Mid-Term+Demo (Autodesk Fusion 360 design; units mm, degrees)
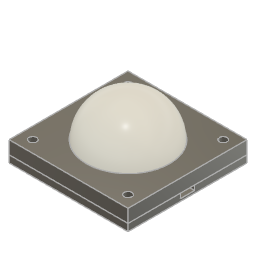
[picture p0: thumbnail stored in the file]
sketch "Sketch1" plane through (0, 0, 0) normal (0, 1, 0) x axis (1, 0, 0)
  line L1 (0, 45) -> (0, 0)
  line L2 (0, -35) -> (0, 0)
  circle C1 centre (0, 0) radius 15
  circle C2 centre (0, 0) radius 17.5
  circle C3 centre (0, 0) radius 22.5
  point P1 (0, 0)
  point P2 (0, 0)
  point P4 (0, 0)
  point P6 (0, 0)
  coincident P1 P2
  concentric C1 C2
  coincident P1 P4
  vertical L1
  coincident P2 P6
  parallel L1 L2
  concentric C2 C3
  dimension "d1" diameter C1 = 30
  dimension "d2" diameter C2 = 35
  dimension "d4" diameter C3 = 45
revolve "Revolve1" sketch "Sketch1" AlongAngle 180 bodies "Membrane"
extrude "Extrude1" add blind -5
move "Move1"
sketch "Sketch2" plane through (0, 0, 0) normal (0, 1, 0) x axis (1, 0, 0)
  line L1 (25, 25) -> (-25, 25)
  line L2 (25, -25) -> (25, 25)
  line L3 (-25, -25) -> (25, -25)
  line L4 (-25, 25) -> (-25, -25)
  circle C1 centre (0, 0) radius 22.5
  point P1 (0, 0)
  point P2 (0, 0)
  coincident P1 P2
  horizontal L1
  vertical L2
  horizontal L3
  vertical L4
  dimension "d7" diameter C1 = 45
extrude "Extrude2" new body sketch "Sketch2" along normal blind 3.5 bodies "Cap"
sketch "Sketch3" plane through (0, 3.5, 0) normal (0, 1, 0) x axis (-1, 0, 0)
  line L1 (-25, 25) -> (25, 25)
  line L2 (-25, -25) -> (-25, 25)
  line L3 (25, -25) -> (-25, -25)
  line L4 (25, 25) -> (25, -25)
  circle C1 centre (0, 0) radius 22.5
  circle C2 centre (0, 0) radius 17.5
  concentric C1 C2
  dimension "d10" diameter C2 = 35
extrude "Extrude3" add sketch "Sketch3" along normal blind 2
extrude "Extrude4" new body sketch "Sketch2" against normal blind 8 bodies "Base"
sketch "Sketch4" plane through (0, 0, 0) normal (0, 1, 0) x axis (-1, 0, 0)
  line L1 (-25, 25) -> (25, 25)
  line L2 (-25, -25) -> (-25, 25)
  line L3 (25, -25) -> (-25, -25)
  line L4 (25, 25) -> (25, -25)
  line L5 (-6, -0.9751) -> (-25, -0.9751)
  line L6 (0, 1.0068) -> (0, -0.9751)
  line L7 (-25, 1.0068) -> (-6, 1.0068)
  line L8 (0, 8) -> (0, 0)
  line L9 (5.4, 8) -> (-6, 8)
  line L10 (5.4, -8) -> (5.4, 8)
  line L11 (-6, -8) -> (5.4, -8)
  line L12 (-6, -0.9751) -> (-6, -8)
  line L13 (-6, 8) -> (-6, 1.0068)
  circle C1 centre (0, 0) radius 17.5
  circle C2 centre (0, 0) radius 20
  point P6 (-25, -0.9751)
  point P9 (-25, 1.0068)
  point P1 (0, 0)
  point P10 (0, 0)
  point P16 (-6, 1.0068)
  point P18 (0, 0)
  point P19 (0, 0)
  point P11 (0, 8)
  point P12 (-6, 8)
  point P13 (5.4, 8)
  coincident L2 P6
  perpendicular L2 L5
  perpendicular L5 L6
  coincident L2 P9
  perpendicular L2 L7
  coincident P1 P10
  parallel L6 L8
  horizontal L9
  vertical L10
  horizontal L11
  vertical L12
  coincident P16 L12
  collinear L12 L13
  coincident P1 P18
  coincident P10 P19
  dimension "d17" distance P10 P11 = 8
  dimension "d18" distance P12 P13 = 11.4
  dimension "d19" distance L2 L13 = 19
  dimension "d20" diameter C1 = 35
  dimension "d23" diameter C2 = 40
extrude "Extrude6" cut sketch "Sketch4" profile of L2 L5 L7 L9 L10 L11 L13 C1 C2 against normal blind 1
sketch "Sketch5" plane through (0, 5.5, 0) normal (0, 1, 0) x axis (-1, 0, 0)
  line L1 (25, 25) -> (25, -25)
  line L2 (-25, 25) -> (25, 25)
  line L3 (-25, -25) -> (-25, 25)
  line L4 (25, -25) -> (-25, -25)
  line L5 (-25, 25) -> (25, -25)
  line L6 (25, 25) -> (-25, -25)
  line L7 (-20, -20) -> (20, -20)
  line L8 (-20, 20) -> (-20, -20)
  line L9 (20, 20) -> (-20, 20)
  line L10 (20, -20) -> (20, 20)
  circle C1 centre (0, 0) radius 17.5
  point P3 (25, -25)
  point P7 (25, -25)
  point P5 (-25, 25)
  point P8 (-25, 25)
  point P6 (-25, -25)
  point P9 (-25, -25)
  point P4 (25, 25)
  point P10 (25, 25)
  point P13 (-20, 20)
  point P11 (20, -20)
  coincident P3 P7
  coincident P5 P8
  coincident P6 P9
  coincident P4 P10
  horizontal L7
  vertical L8
  horizontal L9
  vertical L10
  coincident L5 P13
  coincident L5 P11
sketch "Sketch6" plane through (0, -8, 0) normal (0, -1, 0) x axis (1, 0, 0)
  line L1 (-25, 25) -> (25, 25)
  line L2 (-25, -25) -> (-25, 25)
  line L3 (25, -25) -> (-25, -25)
  line L4 (25, 25) -> (25, -25)
  line L5 (-18.35, 22.6847) -> (-16.8, 20)
  line L6 (-21.45, 22.6847) -> (-18.35, 22.6847)
  line L7 (-23, 20) -> (-21.45, 22.6847)
  line L8 (-21.45, 17.3153) -> (-23, 20)
  line L9 (-18.35, 17.3153) -> (-21.45, 17.3153)
  line L10 (-16.8, 20) -> (-18.35, 17.3153)
  line L11 (21.65, 22.6847) -> (23.2, 20)
  line L12 (18.55, 22.6847) -> (21.65, 22.6847)
  line L13 (17, 20) -> (18.55, 22.6847)
  line L14 (18.55, 17.3153) -> (17, 20)
  line L15 (21.65, 17.3153) -> (18.55, 17.3153)
  line L16 (23.2, 20) -> (21.65, 17.3153)
  line L17 (-22.6847, -18.45) -> (-20, -16.9)
  line L18 (-22.6847, -21.55) -> (-22.6847, -18.45)
  line L19 (-20, -23.1) -> (-22.6847, -21.55)
  line L20 (-17.3153, -21.55) -> (-20, -23.1)
  line L21 (-17.3153, -18.45) -> (-17.3153, -21.55)
  line L22 (-20, -16.9) -> (-17.3153, -18.45)
  line L23 (17.3153, -18.45) -> (20, -16.9)
  line L24 (17.3153, -21.55) -> (17.3153, -18.45)
  line L25 (20, -23.1) -> (17.3153, -21.55)
  line L26 (22.6847, -21.55) -> (20, -23.1)
  line L27 (22.6847, -18.45) -> (22.6847, -21.55)
  line L28 (20, -16.9) -> (22.6847, -18.45)
  point P6 (-16.8, 20)
  point P12 (-19.9, 20)
  point P13 (23.2, 20)
  point P19 (20.1, 20)
  point P20 (-20, -16.9)
  point P26 (-20, -20)
  point P27 (20, -16.9)
  point P33 (20, -20)
  dimension "d24" distance P6 P12 = 3.1
  dimension "d25" distance P13 P19 = 3.1
  dimension "d26" distance P20 P26 = 3.1
  dimension "d27" distance P27 P33 = 3.1
extrude "Extrude7" cut sketch "Sketch6" profile of L5 L6 L7 L8 L9 L10 L11 L12 L13 L14 L15 L16 L17 L18 L19 L20 L21 L22 L23 L24 L25 L26 L27 L28 against normal blind 2.8
hole "Hole1" HoleDepth 12 HoleDiameter 3.2 TipAngle 180
extrude "Extrude8" cut sketch "Sketch4" profile of L5 L7 C1 C2 against normal blind 0.5
sketch "Sketch7" plane through (0, 0, 0) normal (0, 1, 0) x axis (1, 0, 0)
  line L1 (25, 25) -> (-25, 25)
  line L2 (25, -25) -> (25, 25)
  line L3 (-25, -25) -> (25, -25)
  line L4 (-25, 25) -> (-25, -25)
  horizontal L1
  vertical L2
  horizontal L3
  vertical L4
combine "Combine1"
sketch "Sketch8" plane through (0, 0, 0) normal (0, -1, 0) x axis (1, 0, 0)
  line L1 (25, 25) -> (-25, 25)
  line L2 (25, -25) -> (25, 25)
  line L3 (-25, -25) -> (25, -25)
  line L4 (-25, 25) -> (-25, -25)
  circle C1 centre (0, 0) radius 15
  circle C2 centre (0, 0) radius 22.5
  circle C3 centre (-0.0783, 18.7498) radius 3.75
  circle C4 centre (-0.0153, -20.25) radius 2.25
  point P1 (0, 0)
  point P7 (0, 0)
  horizontal L1
  vertical L2
  horizontal L3
  vertical L4
  coincident P1 P7
  tangent C1 C3
  dimension "d39" diameter C2 = 45
extrude "Extrude1" add sketch "Sketch8" profile of C1 L1 L2 L3 L4 along normal blind 5
extrude "Extrude2" cut sketch "Sketch8" profile of C2 C3 C4 along normal blind 10
sketch "Sketch9" plane through (0, -5, 0) normal (0, -1, 0) x axis (1, 0, 0)
  line L1 (25, -25) -> (-25, -25)
  line L2 (25, 25) -> (25, -25)
  line L3 (-25, 25) -> (25, 25)
  line L4 (-25, -25) -> (-25, 25)
  line L5 (25, -25) -> (-25, 25)
  line L6 (-25, -25) -> (25, 25)
  line L7 (21, 21) -> (-21, 21)
  line L8 (21, -21) -> (21, 21)
  line L9 (-21, -21) -> (21, -21)
  line L10 (-21, 21) -> (-21, -21)
  circle C1 centre (-0.0783, 18.7498) radius 3.75
  arc A1 centre (0, 0) radius 22.5 clockwise from (-0.0034, -22.5) to (-0.0307, -22.5)
  arc A2 centre (-0.0153, -20.25) radius 2.25 clockwise from (-0.0307, -22.5) to (-0.0034, -22.5)
  circle C2 centre (0, 0) radius 22.5
  point P1 (0, 0)
  point P11 (0, 0)
  point P10 (-25, 25)
  point P12 (-25, 25)
  point P8 (25, -25)
  point P13 (25, -25)
  point P9 (25, 25)
  point P14 (25, 25)
  point P7 (-25, -25)
  point P15 (-25, -25)
  point P18 (21, -21)
  point P16 (-21, 21)
  coincident P1 P11
  tangent C1 C2
  coincident P10 P12
  coincident P8 P13
  coincident P9 P14
  coincident P7 P15
  horizontal L7
  vertical L8
  horizontal L9
  vertical L10
  coincident L5 P18
  coincident L5 P16
hole "Hole1" HoleDepth 31 HoleDiameter 3.2 TipAngle 180
sketch "Sketch10" plane through (0, 25, 0) normal (0, 1, 0) x axis (-1, 0, 0)
  line L1 (-25, 25) -> (25, 25)
  line L2 (-25, -25) -> (-25, 25)
  line L3 (25, -25) -> (-25, -25)
  line L4 (25, 25) -> (25, -25)
  line L5 (23.6847, -22.55) -> (21, -24.1)
  line L6 (23.6847, -19.45) -> (23.6847, -22.55)
  line L7 (21, -17.9) -> (23.6847, -19.45)
  line L8 (18.3153, -19.45) -> (21, -17.9)
  line L9 (18.3153, -22.55) -> (18.3153, -19.45)
  line L10 (21, -24.1) -> (18.3153, -22.55)
  line L11 (-18.3153, -22.55) -> (-21, -24.1)
  line L12 (-18.3153, -19.45) -> (-18.3153, -22.55)
  line L13 (-21, -17.9) -> (-18.3153, -19.45)
  line L14 (-23.6847, -19.45) -> (-21, -17.9)
  line L15 (-23.6847, -22.55) -> (-23.6847, -19.45)
  line L16 (-21, -24.1) -> (-23.6847, -22.55)
  line L17 (-18.3153, 19.45) -> (-21, 17.9)
  line L18 (-18.3153, 22.55) -> (-18.3153, 19.45)
  line L19 (-21, 24.1) -> (-18.3153, 22.55)
  line L20 (-23.6847, 22.55) -> (-21, 24.1)
  line L21 (-23.6847, 19.45) -> (-23.6847, 22.55)
  line L22 (-21, 17.9) -> (-23.6847, 19.45)
  line L23 (23.6847, 19.45) -> (21, 17.9)
  line L24 (23.6847, 22.55) -> (23.6847, 19.45)
  line L25 (21, 24.1) -> (23.6847, 22.55)
  line L26 (18.3153, 22.55) -> (21, 24.1)
  line L27 (18.3153, 19.45) -> (18.3153, 22.55)
  line L28 (21, 17.9) -> (18.3153, 19.45)
  circle C1 centre (-21, -21) radius 1.6
  circle C2 centre (21, 21) radius 1.6
  circle C3 centre (-21, 21) radius 1.6
  circle C4 centre (21, -21) radius 1.6
  point P5 (21, -21)
  point P16 (21, -21)
  point P2 (-21, -21)
  point P23 (-21, -21)
  point P4 (-21, 21)
  point P30 (-21, 21)
  point P3 (21, 21)
  point P37 (21, 21)
  point P10 (21, -24.1)
  point P17 (-21, -24.1)
  point P24 (-21, 17.9)
  point P31 (21, 17.9)
  coincident P5 P16
  coincident P2 P23
  coincident P4 P30
  coincident P3 P37
  dimension "d45" distance P10 P16 = 3.1
  dimension "d46" distance P17 P23 = 3.1
  dimension "d47" distance P24 P30 = 3.1
  dimension "d48" distance P31 P37 = 3.1
extrude "Extrude3" cut sketch "Sketch10" profile of C1 C2 C3 C4 L5 L6 L7 L8 L9 L10 L11 L12 L13 L14 L15 L16 L17 L18 L19 L20 L21 L22 L23 L24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 against normal blind 3
extrude "Extrude9" cut of existing geometry blind -1
sketch "Sketch11" plane through (0, -2, 0) normal (0, 1, 0) x axis (-1, 0, 0)
  line L1 (-25, 1.0068) -> (-17.471, 1.0068)
  line L2 (-25, -0.9751) -> (-25, 1.0068)
  line L3 (-17.4728, -0.9751) -> (-25, -0.9751)
  line L4 (-16.4984, 3) -> (-25.5767, 3)
  line L5 (-16.4984, -3.0369) -> (-16.4984, 3)
  line L6 (-25.5767, -3.0369) -> (-16.4984, -3.0369)
  line L7 (-25.5767, 3) -> (-25.5767, -3.0369)
  arc A1 centre (0, 0) radius 17.5 clockwise from (-17.471, 1.0068) to (-17.4728, -0.9751)
  horizontal L4
  vertical L5
  horizontal L6
  vertical L7
extrude "Extrude10" cut sketch "Sketch11" along normal blind 3
extrude "Extrude11" cut of existing geometry blind -4
extrude "Extrude12" cut of existing geometry blind -5
sketch "Sketch12" plane through (0, -2, 0) normal (0, 1, 0) x axis (-1, 0, 0)
  line L1 (-25, 3) -> (-17.2409, 3)
  line L2 (-25, -3.0369) -> (-25, 3)
  line L3 (-17.2345, -3.0369) -> (-25, -3.0369)
  line L4 (-16, 3) -> (-17.2409, 3)
  line L5 (-15.993, -3.0369) -> (-17.2345, -3.0369)
  arc A1 centre (0, 0) radius 17.5 clockwise from (-17.2409, 3) to (-17.2345, -3.0369)
  circle C1 centre (0, 0) radius 16.2788
  point P2 (-17.2409, 3)
  point P8 (-17.2409, 3)
  point P9 (-16, 3)
  point P5 (-17.2345, -3.0369)
  point P10 (-17.2345, -3.0369)
  point P11 (-15.993, -3.0369)
  concentric A1 C1
  coincident P2 P8
  coincident C1 P9
  parallel L1 L4
  coincident P5 P10
  coincident C1 P11
  parallel L3 L5
extrude "Extrude13" add sketch "Sketch12" profile of A1 C1 L4 L5 along normal blind 1
offset_faces "OffsetFaces1" distance -1
extrude "Extrude14" add of existing geometry blind 0.5
extrude "Extrude15" add of existing geometry blind 0.5
offset_faces "OffsetFaces2" distance 1
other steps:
create_component "CreateComponent2"
named bodies: "Membrane", "Cap", "Base"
